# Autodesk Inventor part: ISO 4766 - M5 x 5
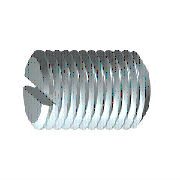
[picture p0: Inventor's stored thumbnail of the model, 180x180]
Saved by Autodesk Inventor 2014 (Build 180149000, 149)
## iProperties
IsCustomPart: 0
Created: 2008-01
Part Number: ISO 4766 - M5 x 5
Material: Stainless Steel, 440C
Description: Slotted Headless Set Screw - Flat Point
Document SubType Name: Modeling
Standard: ISO 4766
Designer: latalom
Standard Revision: First edition 1983-09-01
Standards Organization: ISO
Language: en-US
Size Designation: M5 x 5
Categories: <MemberInstance><Categories><Category DisplayName="Fasteners" InternalName="e4da775c-781d-43d5-af7c-5136215cf5a6" Mnemonic="FSTN"><Category DisplayName="Bolts"
Density: 7.75 g/cm^3
Mass: 0.682426 g
Surface Area: 1.16465 cm^2
Volume: 0.088055 cm^3
Appearance: Steel
Author: latalom
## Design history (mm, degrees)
sketch "Sketch1"
  geometry: L1 (0, 0)-(5, 0); L2 (5, 0)-(5, 2.5); L3 (5, 2.5)-(0, 2.5); L4 (0, -0.5)-(0, 3) reference; L5 (0, 2.5)-(0, 0)
  constraints: 9 end point, 2 parallel, 2 perpendicular, 1 collinear, 1 point on line
  dimensions: "d0" = 5 diameter of L3 L1 (= NND); "d2" = 5 distance from line of L2 L3.end (= NLG)
revolve "Body" sketch "Sketch1" stored, may be unused: angle "d6" = 90 deg
sketch "Sketch2"
  geometry: L1 (5, 2.009)-(5, -2.009) reference; L2 (3.464, 0)-(5.256, 0) reference; L3 (5, 0.4)-(3.72, 0.4); L4 (3.72, 0.4)-(3.72, 0); L5 (3.72, -0.4)-(3.72, 0); L6 (3.72, -0.4)-(5, -0.4)
  constraints: 8 end point, 3 point on line, 2 perpendicular, 1 parallel, 1 symmetric about line, 1 other
  dimensions: "d8" = 0.4 distance between parallel lines of L2 L3 (= 0.5 x SBR); "d9" = 1.28 distance between parallel lines of L1 L4 (= STI)
extrude "Slot1" cut sketch "Sketch2" stored distance "d10" = 5 (= NND); taper "d11" = 0 deg
workaxis "Work Axis1"
workplane "Work Plane1"
body "Solid1"
chamfer "Chamfer1" distance "d3" = 0.49076 (= -0.5 x GD1 + 0.5 x NND); stored, may be unused: angle "d4" = 60 deg (= FAWI), second distance "d34" = 0.49076 (= -0.5 x GD1 + 0.5 x NND)
feature "Thread" dims "d5" = 5 (= NLG), "d7" = 0
chamfer "Chamfer2" distance "d13" = 0.43301 (computed from NND, SPD, FAWI); stored, may be unused: angle "d14" = 60 deg (= FAWI), second distance "d35" = 0.43301 (computed from NND, SPD, FAWI)
other parameters: "NND" = 5 [user parameter; used in 6 equation terms], "NLG" = 5 [user parameter; used in 2 equation terms], "FAWI" = 60 deg [user parameter; used in 4 equation terms], "GD1" = 4.01848 (= THREADDIA - 1.2269 x PTC) [user parameter; used in 2 equation terms], "d1" = 0, "FAWI1" = 45 deg [user parameter], "SPD" = 3.5 [user parameter; used in 2 equation terms], "SBR" = 0.8 [user parameter; used in 1 equation term], "STI" = 1.28 [user parameter; used in 1 equation term], "d15" = 0, "d36" = 90 deg, "d37" = 0, "GUL" = 0.49076 (= 0.61345 x PTC) [user parameter], "TPU" = 12.5 (computed from PTC) [user parameter], "THREADDIA" = 5 [user parameter; used in 1 equation term], "TOA" = 30 deg [user parameter], "PTC" = 0.8 [user parameter; used in 4 equation terms], "GAL" = 0.49076 (= 0.61345 x PTC) [user parameter]
